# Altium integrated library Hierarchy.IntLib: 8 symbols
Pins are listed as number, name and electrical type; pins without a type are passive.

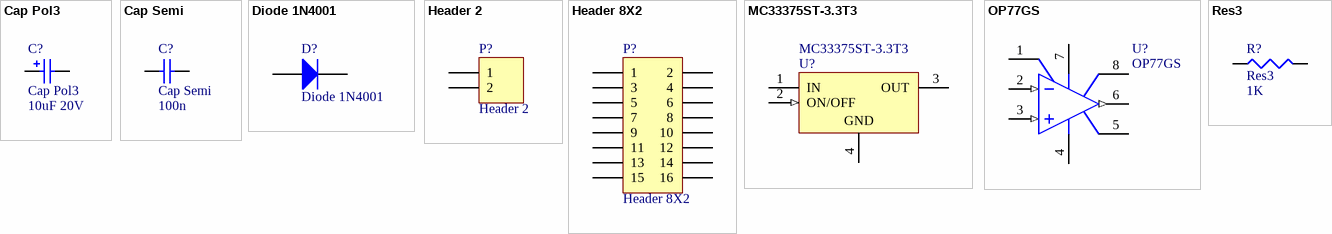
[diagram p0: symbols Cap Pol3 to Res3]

## Cap Pol3
designator C?  value 10uF 20V
Polarized Capacitor (Surface Mount)
footprint C0805 (Chip Capacitor, Body 2.0x1.3mm, IPC High Density)
footprint 1812 (Chip Capacitor, Body 4.5x3.2mm, IPC High Density)
footprint 1825 (Chip Capacitor, Body 4.5x6.4mm, IPC High Density)
footprint C2225 (Chip Capacitor, Body 5.7x6.4mm, IPC High Density)
footprint 2220 (Chip Capacitor, Body 5.7x5.0mm, IPC High Density)
simulation model CAP (Capacitor)
signal-integrity model Cap Pol
pins: 1, 2
1 alternate drawing of the same symbol

## Cap Semi
designator C?  value 100n
Capacitor (Semiconductor SIM Model)
footprint C1206 (Chip Capacitor, Body 3.2x1.6mm, IPC High Density)
footprint 0402 (Chip Capacitor, Body 1.0x0.5mm, IPC High Density)
footprint C2512 (Chip Capacitor, Body 2.54x1.27mm, IPC High Density)
footprint 1608[0603] (Chip Capacitor, Body 1.6x0.8mm, IPC High Density)
footprint C1210 (Chip Capacitor, Body 3.2x2.5mm, IPC High Density)
simulation model CAP (Semiconductor Capacitor)
signal-integrity model Cap Semi
pins: 1, 2

## Diode 1N4001
designator D?
1 Amp General Purpose Rectifier
footprint DO-41 (Diode, Axial; Body 5.2 x 2.7 mm (LxDia. max), Lead Dia. 0.86 mm (max))
signal-integrity model 1N4001
pins: 1 A, 2 K

## Header 2
designator P?
Header, 2-Pin
footprint HDR1X2 (Connector; Header; 2 Position)
signal-integrity model Connector
pins: 1, 2

## Header 8X2
designator P?
Header, 8-Pin, Dual row
footprint HDR2X8 (Connector; Header; 8x2 Position)
signal-integrity model Connector
pins: 1, 2, 3, 4, 5, 6, 7, 8, 9, 10, 11, 12, 13, 14, 15, 16

## MC33375ST-3.3T3
designator U?
Low Dropout 300mA Voltage Regulator with ON/OFF Control
footprint 318E-04 (SOT-223/SC-73; 4 Leads; Body 6.7 x 7.3 mm, inc. leads (LxW max))
pins: 1 IN (power), 2 ON/OFF (in), 3 OUT (power), 4 GND (power)

## OP77GS
designator U?
Ultra-Low Offset Voltage Operational Amplifier; Note: Pin 5 is not connected.
footprint SO-8_N (SOIC, 8-Leads, Body 4.9x3.9mm, Pitch 1.27mm, IPC Medium Density)
footprint SO-8_L (SOIC, 8-Leads, Body 4.9x3.9mm, Pitch 1.27mm, IPC High Density)
footprint SO-8_M (SOIC, 8-Leads, Body 4.9x3.9mm, Pitch 1.27mm, IPC Low Density)
3D model SO-8 (8-Pin Small Outline Integrated Circuit 1.27 mm Pitch)
simulation model OP77G (SUBCKT)
pins: 1 VOSTRIM, 2 IN- (in), 3 IN+ (in), 4 V- (power), 5 NC, 6 OUT (out), 7 V+ (power), 8 VOSTRIM

## Res3
designator R?  value 1K
Resistor
footprint J1-0603 (Chip Resistor, Body 1.6x0.8mm, IPC High Density)
footprint 14-1210 (Chip Resistor, Body 3.2x2.5mm, IPC High Density)
footprint 12Z-2010 (Chip Resistor, Body 5.0x2.5mm, IPC High Density)
footprint RESC6332 (Chip Resistor, Body 6.3x3.2mm, IPC High Density)
simulation model RESISTOR (Resistor)
signal-integrity model Res
pins: 1, 2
